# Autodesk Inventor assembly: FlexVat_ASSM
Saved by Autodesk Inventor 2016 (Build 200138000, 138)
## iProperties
Created: 2015-11
Part Number: FlexVat_ASSM
Document SubType Name: Assembly
Designer: John
Author: John
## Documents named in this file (8)
- D:\3D Printer Designs\John Ledden Designs\DLP Printer\V0-4\FlexVat_ASSM.iam
- D:\3D Printer Designs\John Ledden Designs\DLP Printer\V0-4\FlexVat_Base.ipt
- D:\3D Printer Designs\John Ledden Designs\DLP Printer\V0-4\Clear_VatBottom.ipt
- D:\3D Printer Designs\John Ledden Designs\DLP Printer\V0-4\FEP_Film.ipt
- D:\3D Printer Designs\John Ledden Designs\DLP Printer\V0-4\Clamp_Bottom.ipt
- D:\3D Printer Designs\John Ledden Designs\DLP Printer\V0-4\Gasket_Strip.ipt
- D:\3D Printer Designs\John Ledden Designs\DLP Printer\V0-4\Clamp_Top.ipt
- D:\3D Printer Designs\John Ledden Designs\DLP Printer\V0-4\VatWall.ipt
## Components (13 placed, 13 different names)
1. FlexVat_Base_1070
2. Clear_VatBottom_1071
3. FEP_Film_1072
4. Clamp_Bottom_1073
5. Gasket_Strip_1074
6. Gasket_Strip_1075
7. Gasket_Strip_1076
8. Gasket_Strip_1077
9. Clamp_Top_1078
10. VatWall_1079
11. VatWall_1080
12. VatWall_1081
13. VatWall_1082
